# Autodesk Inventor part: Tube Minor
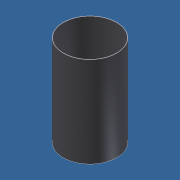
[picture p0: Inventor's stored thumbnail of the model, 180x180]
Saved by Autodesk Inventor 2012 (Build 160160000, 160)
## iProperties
Category: Mechanical Engineering Drawing and Design - CADD
Manager: Fábio Ricardo de Oliveira Souza
Company: SENAI - Serviço Nacional de Aprendizagem Industrial
Created: 2011-06
Part Number: Tube Minor
Material: Steel
Description: Stainless Steel (DIN- X6CrNiTi18-10)
Document SubType Name: Modeling
Designer: Guilherme Augusto Franco de Souza
Engineer: George Geraldo de Oliveia Silva
Authority: Fábio Ricardo de Oliveira Soza
Density: 7.85 g/cm^3
Subject: WorldSkill 2011 - London, England
Author: Guilherme Augusto Franco de Souza
Revision Number: 00
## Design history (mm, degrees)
sketch "Sketch2"
  geometry: C1 r 74 at (0, 0); 1 further point
  constraints: 1 centre point, 1 coincident
  dimensions: "Diam_ext" = 148 diameter of C1
extrude "Extrusion2" new body sketch "Sketch2" taper "d4" = 0 deg; stored distance "Comp" = 250
shell "Shell1" dims "d5" = 1
sketch "Sketch3"
  geometry: L1 (-74, 125)-(74, 125) reference; L2 (-62.5, 125)-(62.5, 125); L3 (62.5, 125)-(62.5, 100); L4 (62.5, 100)-(-62.5, 100); L5 (-62.5, 100)-(-62.5, 125); 2 further points
  constraints: 8 end point, 2 midpoint, 2 parallel, 1 horizontal, 1 perpendicular, 1 point on line
  dimensions: "d6" = 25 distance of L2.end L3.end; "d7" = 125 distance of L3.end L4.end
extrude "Extrusion3" cut sketch "Sketch3" stored distance "d8" = 350; taper "d9" = 0 deg
pattern_circular "Circular Pattern1" dims angle "d11" = 90 deg
body "Solid2"
